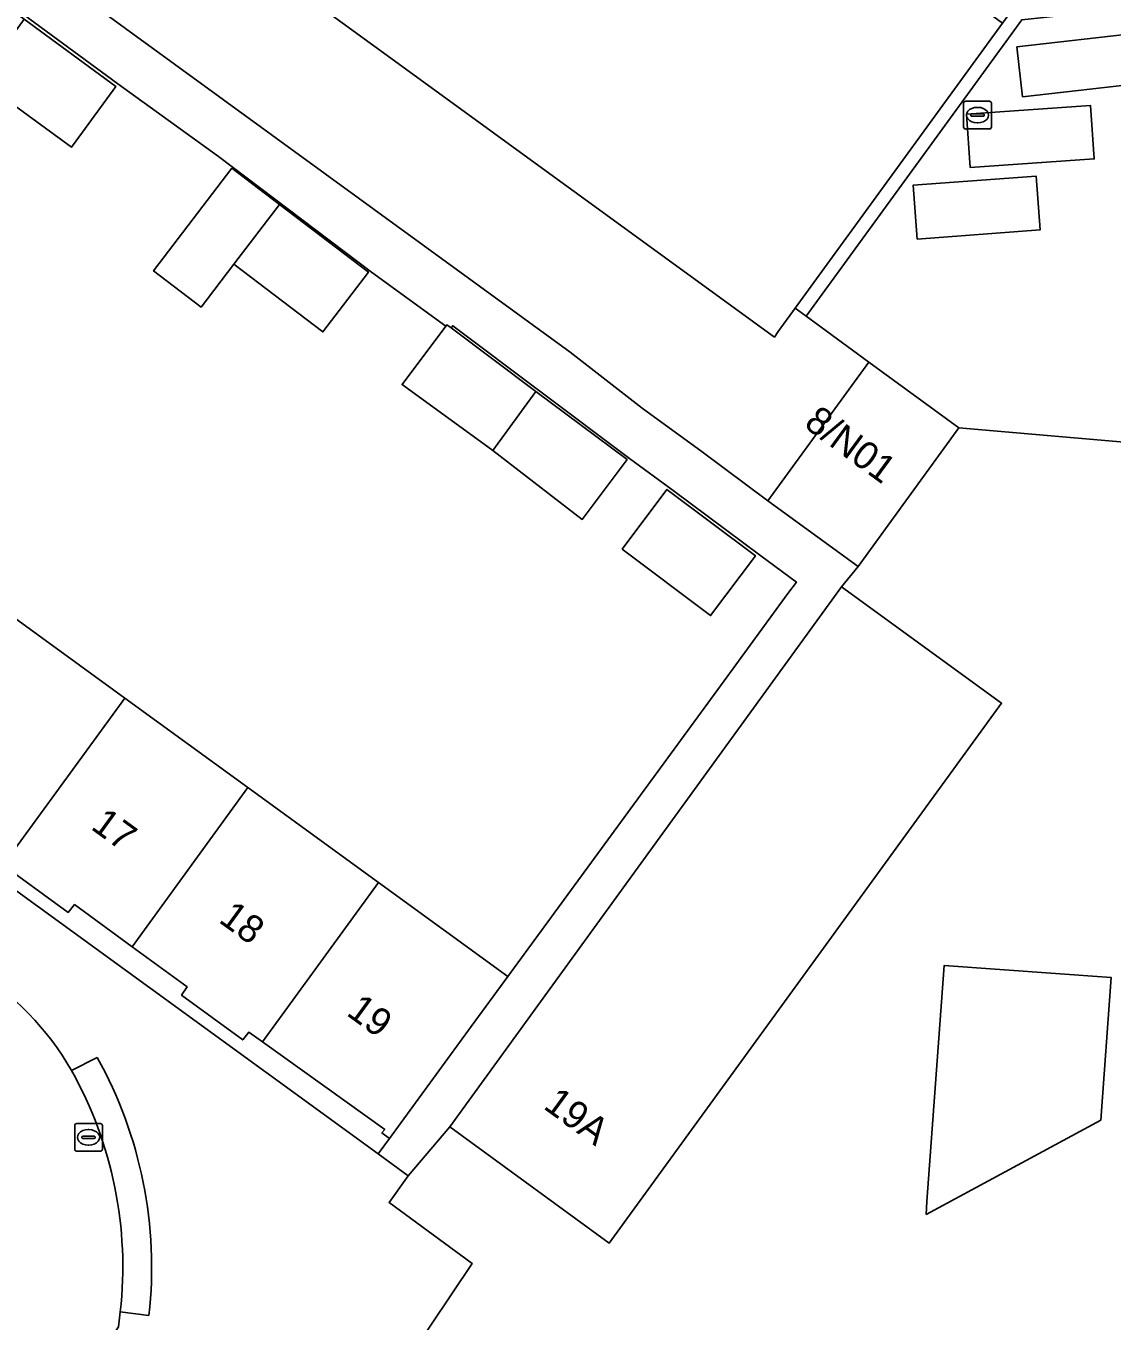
# Model space of a CAD drawing. Extents: x 160102 to 160934, y 382045 to 382923.
# Drawn here: x 160464.08 to 160503.26, y 382304.79 to 382351.51 of the extents above; entities that cross this region are included whole.
import ezdxf

# ---------------------------------------------------------------- set-up
doc = ezdxf.new("R2010")
doc.units = 0
for name, color, linetype in [('IMGEO_Erf', 7, 'Continuous'), ('IMGEO_Kolk', 7, 'Continuous'), ('IMGEO_Pand', 7, 'Continuous'), ('IMGEO_Pand_nummerreeks', 7, 'Continuous'), ('IMGEO_Parkeervlak_open', 7, 'Continuous'), ('IMGEO_Rijbaan_lokaal_open', 7, 'Continuous'), ('IMGEO_Rioolput', 7, 'Continuous'), ('IMGEO_Voetpad_open', 7, 'Continuous')]:
    doc.layers.add(name, color=color, linetype=linetype)

msp = doc.modelspace()

# ---------------------------------------------------------------- linework, layer by layer
at = {"layer": 'IMGEO_Erf'}
for points in [[(160460.587, 382356.574), (160483.716, 382339.75), (160486.31, 382337.728), (160488.477, 382336.147), (160490.845, 382334.379), (160494.484, 382339.385), (160492.767, 382340.642), (160492.226, 382341.039), (160491.833, 382341.328), (160491.222, 382340.488), (160491.079, 382340.291), (160440.354, 382377.176)], [(160462.864, 382330.742), (160467.643, 382327.268), (160472.086, 382324.039), (160476.795, 382320.616), (160481.466, 382317.222), (160489.264, 382327.886), (160491.567, 382331.035), (160491.874, 382331.454), (160490.59, 382332.393), (160487.43, 382334.758), (160485.852, 382335.907), (160479.476, 382340.697), (160479.42, 382340.621), (160482.477, 382338.332), (160485.764, 382335.871), (160484.148, 382333.713), (160480.926, 382336.2), (160477.838, 382338.449), (160477.651, 382338.577), (160479.225, 382340.68), (160476.542, 382342.636), (160471.028, 382346.804), (160467.398, 382349.424), (160459.402, 382355.308)], [(160503.975, 382336.473), (160497.739, 382337.019), (160494.1, 382332.013), (160493.502, 382331.275), (160499.276, 382327.078), (160485.122, 382307.607), (160479.369, 382311.802), (160477.868, 382310.038), (160477.183, 382309.073), (160480.172, 382306.873), (160477.931, 382303.512), (160462.512, 382280.35)]]:
    msp.add_lwpolyline(points, dxfattribs=at)
for points in [[(160462.41, 382349.561), (160458.992, 382352.063), (160460.597, 382354.255), (160464.014, 382351.753), (160467.327, 382349.327), (160465.894, 382347.369), (160465.723, 382347.135)], [(160473.223, 382345.078), (160476.436, 382342.631), (160474.796, 382340.478), (160471.583, 382342.925), (160470.4, 382341.372), (160468.687, 382342.677), (160471.51, 382346.383)], [(160458.705, 382325.02), (160454.136, 382328.353), (160449.479, 382331.751), (160444.691, 382335.12), (160444.429, 382335.326), (160443.963, 382334.685), (160476.788, 382310.823), (160477.195, 382311.38), (160476.921, 382311.578), (160477.022, 382311.703), (160472.614, 382314.863), (160472.121, 382315.216), (160471.901, 382314.935), (160469.697, 382316.552), (160469.89, 382316.85), (160467.912, 382318.297), (160465.832, 382319.819), (160465.6, 382319.532), (160463.381, 382321.156), (160463.574, 382321.469), (160463.479, 382321.539)], [(160485.588, 382332.634), (160487.204, 382334.793), (160490.395, 382332.404), (160488.779, 382330.245)], [(160496.551, 382308.639), (160496.585, 382309.108), (160497.203, 382317.618), (160503.231, 382317.181), (160502.858, 382312.045)]]:
    msp.add_lwpolyline(points, close=True, dxfattribs=at)
at = {"layer": 'IMGEO_Kolk'}
for p, q in [((160497.908, 382347.87), (160497.908, 382348.722)), ((160497.983, 382348.796), (160498.835, 382348.796)), ((160498.396, 382348.576), (160498.421, 382348.576)), ((160498.909, 382348.722), (160498.909, 382347.87)), ((160498.167, 382348.29), (160498.167, 382348.302)), ((160498.605, 382348.253), (160498.207, 382348.253)), ((160498.21, 382348.339), (160498.608, 382348.339)), ((160498.651, 382348.302), (160498.651, 382348.29)), ((160498.835, 382347.796), (160497.983, 382347.796)), ((160498.419, 382348.016), (160498.394, 382348.016))]:
    msp.add_line(p, q, dxfattribs=at)
for points in [[(160497.908, 382347.87), (160497.908, 382348.722)], [(160497.983, 382348.796), (160498.835, 382348.796)], [(160498.909, 382348.722), (160498.909, 382347.87)], [(160498.835, 382347.796), (160497.983, 382347.796)]]:
    msp.add_lwpolyline(points, dxfattribs=at)
for centre, radius, start, end in [((160497.985, 382348.72), 0.0765, 91.552, 178.448), ((160497.985, 382348.72), 0.0765, 91.552, 178.448), ((160498.833, 382348.72), 0.0765, 1.552, 88.448), ((160498.833, 382348.72), 0.0765, 1.552, 88.448), ((160498.207, 382348.299), 0.0403, 85.8775, 175.7526), ((160498.204, 382348.289), 0.0366, 178.938, 274.7102), ((160498.608, 382348.296), 0.043, 264.8664, 352.4533), ((160498.612, 382348.301), 0.0386, 1.7309, 96.639), ((160497.985, 382347.872), 0.0765, 181.552, 268.448), ((160497.985, 382347.872), 0.0765, 181.552, 268.448), ((160498.833, 382347.872), 0.0765, 271.552, 358.448), ((160498.833, 382347.872), 0.0765, 271.552, 358.448)]:
    msp.add_arc(centre, radius, start, end, dxfattribs=at)
for centre, major_axis, ratio, start_param, end_param in [((160498.395, 382348.296), (-0.387, 0.002), 0.722429, 4.712389, 7.853982), ((160498.42, 382348.296), (-0.39, 0.002), 0.717154, 1.570796, 4.712389)]:
    msp.add_ellipse(centre, major_axis=major_axis, ratio=ratio, start_param=start_param, end_param=end_param, dxfattribs=at)
at = {"layer": 'IMGEO_Pand'}
for points in [[(160479.978, 382368.175), (160478.776, 382366.565), (160468.968, 382373.7), (160470.157, 382375.333), (160467.365, 382377.35), (160466.187, 382375.719), (160456.351, 382382.868), (160457.54, 382384.501), (160454.761, 382386.535), (160453.568, 382384.905), (160448.643, 382388.532), (160440.354, 382377.176), (160491.079, 382340.291), (160491.222, 382340.488), (160491.833, 382341.328), (160499.315, 382351.619), (160494.187, 382355.357), (160495.379, 382356.975), (160492.59, 382358.99), (160491.395, 382357.376), (160481.591, 382364.526), (160482.771, 382366.161)], [(160464.014, 382351.753), (160462.588, 382349.79), (160462.41, 382349.561), (160465.723, 382347.135), (160465.894, 382347.369), (160467.327, 382349.327)], [(160471.583, 382342.925), (160473.223, 382345.078), (160471.51, 382346.383), (160468.687, 382342.677), (160470.4, 382341.372)], [(160473.223, 382345.078), (160471.583, 382342.925), (160474.796, 382340.478), (160476.436, 382342.631)], [(160479.42, 382340.621), (160479.267, 382340.736), (160479.225, 382340.68), (160477.651, 382338.577), (160477.838, 382338.449), (160480.926, 382336.2), (160482.477, 382338.332)], [(160497.739, 382337.019), (160494.484, 382339.385), (160490.845, 382334.379), (160494.1, 382332.013)], [(160482.477, 382338.332), (160480.926, 382336.2), (160484.148, 382333.713), (160485.764, 382335.871)], [(160485.588, 382332.634), (160488.779, 382330.245), (160490.395, 382332.404), (160487.204, 382334.793)], [(160485.122, 382307.607), (160499.276, 382327.078), (160493.502, 382331.275), (160479.369, 382311.802)], [(160458.705, 382325.02), (160463.479, 382321.539), (160467.643, 382327.268), (160462.864, 382330.742)], [(160472.086, 382324.039), (160467.643, 382327.268), (160463.479, 382321.539), (160463.574, 382321.469), (160463.381, 382321.156), (160465.6, 382319.532), (160465.832, 382319.819), (160467.912, 382318.297)], [(160472.086, 382324.039), (160467.912, 382318.297), (160469.89, 382316.85), (160469.697, 382316.552), (160471.901, 382314.935), (160472.121, 382315.216), (160472.614, 382314.863), (160476.795, 382320.616)], [(160472.614, 382314.863), (160477.022, 382311.703), (160476.921, 382311.578), (160477.195, 382311.38), (160480.146, 382315.417), (160481.466, 382317.222), (160476.795, 382320.616)], [(160496.551, 382308.639), (160502.858, 382312.045), (160503.231, 382317.181), (160497.203, 382317.618), (160496.585, 382309.108)]]:
    msp.add_lwpolyline(points, close=True, dxfattribs=at)
at = {"layer": 'IMGEO_Parkeervlak_open'}
for points in [[(160499.831, 382350.756), (160500.036, 382348.96), (160504.468, 382349.465), (160504.264, 382351.261)], [(160498.016, 382348.333), (160498.148, 382346.408), (160502.62, 382346.716), (160502.488, 382348.641)], [(160496.092, 382345.77), (160496.237, 382343.825), (160500.666, 382344.155), (160500.521, 382346.099)]]:
    msp.add_lwpolyline(points, close=True, dxfattribs=at)
at = {"layer": 'IMGEO_Rijbaan_lokaal_open'}
for points in [[(160502.729, 382352.02), (160500.905, 382351.829), (160500.007, 382351.735), (160492.226, 382341.039), (160492.767, 382340.642), (160494.484, 382339.385), (160497.739, 382337.019), (160503.975, 382336.473), (160503.786, 382342.949)], [(160461.691, 382305.827), (160460.518, 382304.092), (160453.615, 382293.741), (160452.931, 382292.724), (160457.422, 382289.591), (160458.105, 382290.597), (160465.113, 382301.149), (160467.42, 382304.585), (160467.484, 382305.128)]]:
    msp.add_lwpolyline(points, dxfattribs=at)
for points in [[(160504.468, 382349.465), (160500.036, 382348.96), (160499.831, 382350.756), (160504.264, 382351.261)], [(160502.62, 382346.716), (160498.148, 382346.408), (160498.016, 382348.333), (160502.488, 382348.641)], [(160500.521, 382346.099), (160500.666, 382344.155), (160496.237, 382343.825), (160496.092, 382345.77)]]:
    msp.add_lwpolyline(points, close=True, dxfattribs=at)
for centre, radius, start, end in [((160456.636, 382308.598), 10.487, 29.9298, 58.1529), ((160453.057, 382306.741), 14.517, 353.6225, 29.2328)]:
    msp.add_arc(centre, radius, start, end, dxfattribs=at)
at = {"layer": 'IMGEO_Rioolput'}
for p, q in [((160465.838, 382310.993), (160465.838, 382311.845)), ((160465.913, 382311.919), (160466.765, 382311.919)), ((160466.326, 382311.699), (160466.351, 382311.699)), ((160466.839, 382311.845), (160466.839, 382310.993)), ((160466.097, 382311.413), (160466.097, 382311.425)), ((160466.535, 382311.376), (160466.137, 382311.376)), ((160466.14, 382311.462), (160466.538, 382311.462)), ((160466.581, 382311.425), (160466.581, 382311.413)), ((160466.765, 382310.919), (160465.913, 382310.919)), ((160466.349, 382311.139), (160466.324, 382311.139))]:
    msp.add_line(p, q, dxfattribs=at)
for points in [[(160465.838, 382310.993), (160465.838, 382311.845)], [(160465.913, 382311.919), (160466.765, 382311.919)], [(160466.839, 382311.845), (160466.839, 382310.993)], [(160466.765, 382310.919), (160465.913, 382310.919)]]:
    msp.add_lwpolyline(points, dxfattribs=at)
for centre, radius, start, end in [((160465.915, 382311.843), 0.0765, 91.552, 178.448), ((160465.915, 382311.843), 0.0765, 91.552, 178.448), ((160466.763, 382311.843), 0.0765, 1.552, 88.448), ((160466.763, 382311.843), 0.0765, 1.552, 88.448), ((160466.137, 382311.422), 0.0403, 85.8775, 175.7526), ((160466.134, 382311.412), 0.0366, 178.938, 274.7102), ((160466.538, 382311.419), 0.043, 264.8664, 352.4533), ((160466.542, 382311.424), 0.0386, 1.7309, 96.639), ((160465.915, 382310.995), 0.0765, 181.552, 268.448), ((160465.915, 382310.995), 0.0765, 181.552, 268.448), ((160466.763, 382310.995), 0.0765, 271.552, 358.448), ((160466.763, 382310.995), 0.0765, 271.552, 358.448)]:
    msp.add_arc(centre, radius, start, end, dxfattribs=at)
for centre, major_axis, ratio, start_param, end_param in [((160466.325, 382311.419), (-0.387, 0.002), 0.722429, 4.712389, 7.853982), ((160466.35, 382311.419), (-0.39, 0.002), 0.717154, 1.570796, 4.712389)]:
    msp.add_ellipse(centre, major_axis=major_axis, ratio=ratio, start_param=start_param, end_param=end_param, dxfattribs=at)
at = {"layer": 'IMGEO_Voetpad_open'}
for points in [[(160407.208, 382426.271), (160406.721, 382425.559), (160409.172, 382423.667), (160414.7, 382419.656), (160423.132, 382413.468), (160423.209, 382413.574), (160423.298, 382413.697), (160424.945, 382412.505), (160425.496, 382412.106), (160425.412, 382411.99), (160425.32, 382411.863), (160426.593, 382410.937), (160439.531, 382401.558), (160451.707, 382392.731), (160451.741, 382392.778), (160498.105, 382359.029), (160502.419, 382355.889), (160499.315, 382351.619), (160491.833, 382341.328), (160492.226, 382341.039), (160500.007, 382351.735), (160500.905, 382351.829), (160502.729, 382352.02)], [(160459.654, 382279.028), (160461.076, 382278.193), (160462.039, 382279.64), (160462.512, 382280.35), (160477.931, 382303.512), (160480.172, 382306.873), (160477.183, 382309.073), (160477.868, 382310.038), (160476.788, 382310.823), (160443.963, 382334.685), (160442.192, 382335.973), (160413.948, 382356.505)], [(160459.402, 382355.308), (160467.398, 382349.424), (160471.028, 382346.804), (160476.542, 382342.636), (160479.225, 382340.68), (160479.267, 382340.736), (160479.42, 382340.621), (160479.476, 382340.697), (160485.852, 382335.907), (160487.43, 382334.758), (160490.59, 382332.393), (160491.874, 382331.454), (160491.567, 382331.035), (160489.264, 382327.886), (160481.466, 382317.222), (160480.146, 382315.417), (160477.195, 382311.38), (160476.788, 382310.823), (160477.868, 382310.038), (160479.369, 382311.802), (160493.502, 382331.275), (160494.1, 382332.013), (160490.845, 382334.379), (160488.477, 382336.147), (160486.31, 382337.728), (160483.716, 382339.75), (160460.587, 382356.574)], [(160466.65, 382314.305), (160465.725, 382313.83)], [(160465.725, 382313.83), (160466.65, 382314.305)], [(160468.516, 382304.999), (160467.484, 382305.128), (160467.42, 382304.585)], [(160467.484, 382305.128), (160468.516, 382304.999)]]:
    msp.add_lwpolyline(points, dxfattribs=at)
for centre, radius, start, end in [((160456.636, 382308.598), 10.487, 29.9298, 58.1529), ((160453.077, 382306.743), 15.537, 353.5536, 29.1231), ((160453.077, 382306.743), 15.537, 353.5536, 29.1231), ((160453.057, 382306.741), 14.517, 353.6225, 29.2328)]:
    msp.add_arc(centre, radius, start, end, dxfattribs=at)

# ---------------------------------------------------------------- texts
at = {"layer": 'IMGEO_Pand_nummerreeks'}
for s, rotation, p in [('8/N01', 323.7462, (160492.105, 382337.072)), ('17', 323.942, (160466.382, 382322.567)), ('18', 323.942, (160470.996, 382319.208)), ('19', 323.942, (160475.604, 382315.852)), ('19A', 323.901, (160482.708, 382312.486))]:
    msp.add_text(s, height=1, rotation=rotation, dxfattribs=at).set_placement(p)

doc.saveas('drawing.dxf')
